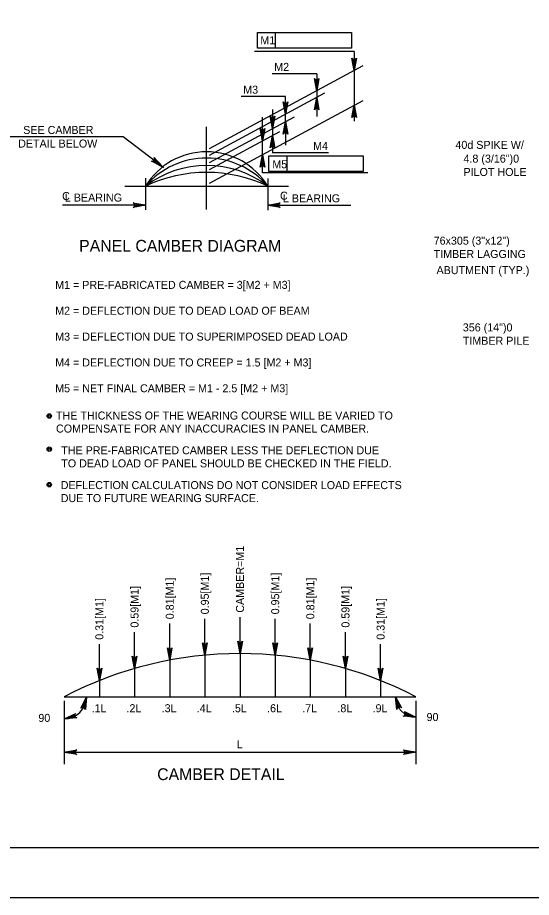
# Model space of a CAD drawing. Extents: x -8 to 75, y -110 to 0.
# Drawn here: x 45.04 to 52.74, y -88 to -74.81 of the extents above; entities that cross this region are included whole.
import ezdxf

# ---------------------------------------------------------------- set-up
doc = ezdxf.new("R2010")
doc.units = 0
for name, color, linetype in [('1', 7, 'Continuous'), ('2', 7, 'Continuous'), ('3', 7, 'Continuous'), ('4', 7, 'Continuous'), ('5', 7, 'Continuous'), ('63', 7, 'Continuous')]:
    doc.layers.add(name, color=color, linetype=linetype)

msp = doc.modelspace()

# ---------------------------------------------------------------- linework, layer by layer
at = {"layer": '1'}
msp.add_lwpolyline([(35.75, -87.25), (67.25, -87.25), (67.25, -66.75), (35.75, -66.75)], close=True, dxfattribs=at)
at = {"layer": '2'}
for p, q in [((46.649, -77.334), (49.101, -77.334)), ((45.742, -84.992), (51.008, -84.992))]:
    msp.add_line(p, q, dxfattribs=at)
at = {"layer": '4'}
for p, q in [((47.848, -84.368), (47.848, -84.992)), ((48.375, -84.344), (48.375, -84.992)), ((48.902, -84.368), (48.902, -84.992)), ((46.795, -84.568), (46.795, -84.992)), ((47.322, -84.442), (47.322, -84.992)), ((49.428, -84.442), (49.428, -84.992)), ((49.955, -84.568), (49.955, -84.992)), ((46.268, -84.749), (46.268, -84.992)), ((50.482, -84.749), (50.482, -84.992)), ((46.268, -84.992), (46.268, -84.992)), ((46.795, -84.992), (46.795, -84.992)), ((47.322, -84.992), (47.322, -84.992)), ((47.848, -84.992), (47.848, -84.992)), ((48.375, -84.992), (48.375, -84.992)), ((48.902, -84.992), (48.902, -84.992)), ((49.428, -84.992), (49.428, -84.992)), ((49.955, -84.992), (49.955, -84.992)), ((50.482, -84.992), (50.482, -84.992))]:
    msp.add_line(p, q, dxfattribs=at)
for centre, radius, start, end in [((47.875, -77.887), 1.069, 31.1159, 148.8841), ((47.875, -78.117), 1.205, 40.5509, 139.4492), ((47.875, -78.53), 1.506, 52.5765, 127.4235), ((47.875, -79.258), 2.13, 64.5513, 115.4487), ((48.375, -90.018), 5.675, 62.3509, 117.6491)]:
    msp.add_arc(centre, radius, start, end, dxfattribs=at)
at = {"layer": '5'}
for p, q in [((48.635, -75.03), (48.909, -75.03)), ((48.635, -75.266), (48.635, -75.03)), ((48.909, -75.266), (48.909, -75.03)), ((48.909, -75.03), (50.047, -75.03)), ((50.047, -75.03), (50.047, -75.266)), ((50.086, -75.315), (48.592, -75.315)), ((50.047, -75.266), (48.635, -75.266)), ((50.086, -75.315), (50.086, -76.358)), ((47.918, -76.771), (50.222, -75.526)), ((49.524, -75.647), (48.858, -75.647)), ((49.524, -75.647), (49.524, -76.29)), ((47.918, -76.87), (49.646, -75.936)), ((49.058, -75.989), (48.391, -75.989)), ((49.058, -76.413), (49.058, -75.989)), ((47.918, -77.291), (50.222, -76.047)), ((48.862, -76.184), (48.862, -76.832)), ((47.918, -76.981), (49.19, -76.294)), ((48.71, -77.136), (48.71, -76.298)), ((47.875, -77.684), (47.875, -76.446)), ((47.918, -77.085), (48.971, -76.516)), ((49.058, -76.413), (49.058, -76.719)), ((46.624, -76.593), (44.917, -76.593)), ((47.216, -77.044), (46.624, -76.593)), ((48.806, -76.879), (49.08, -76.879)), ((48.806, -77.115), (48.806, -76.879)), ((49.703, -76.832), (48.862, -76.832)), ((49.08, -77.115), (49.08, -76.879)), ((49.08, -76.879), (50.218, -76.879)), ((50.218, -76.879), (50.218, -77.115)), ((50.291, -77.136), (48.71, -77.136)), ((50.218, -77.115), (48.806, -77.115)), ((46.96, -77.212), (46.96, -77.689)), ((48.79, -77.218), (48.79, -77.694)), ((46.96, -77.62), (45.714, -77.62)), ((48.79, -77.62), (50.036, -77.62)), ((47.322, -84.442), (47.322, -83.894)), ((47.848, -84.368), (47.848, -83.82)), ((48.375, -84.344), (48.375, -83.795)), ((48.902, -84.368), (48.902, -83.82)), ((49.428, -84.442), (49.428, -83.894)), ((46.795, -84.568), (46.795, -84.02)), ((49.955, -84.568), (49.955, -84.02)), ((46.268, -84.749), (46.268, -84.201)), ((50.482, -84.749), (50.482, -84.201)), ((45.742, -85.054), (45.742, -86.002)), ((51.008, -85.054), (51.008, -86.002)), ((45.742, -85.822), (51.008, -85.822))]:
    msp.add_line(p, q, dxfattribs=at)
for points in [[(50.086, -75.599), (50.051, -75.413), (50.061, -75.427), (50.074, -75.434), (50.086, -75.436), (50.099, -75.434), (50.111, -75.427), (50.121, -75.413), (50.086, -75.599), (50.111, -75.427), (50.099, -75.434), (50.086, -75.599), (50.086, -75.436), (50.074, -75.434), (50.086, -75.599), (50.061, -75.427)], [(49.524, -75.903), (49.489, -75.717), (49.499, -75.731), (49.511, -75.738), (49.524, -75.74), (49.536, -75.738), (49.549, -75.731), (49.558, -75.717), (49.524, -75.903), (49.549, -75.731), (49.536, -75.738), (49.524, -75.903), (49.524, -75.74), (49.511, -75.738), (49.524, -75.903), (49.499, -75.731)], [(49.058, -76.254), (49.023, -76.067), (49.033, -76.082), (49.046, -76.089), (49.058, -76.091), (49.071, -76.089), (49.083, -76.082), (49.093, -76.067), (49.058, -76.254), (49.083, -76.082), (49.071, -76.089), (49.058, -76.254), (49.058, -76.091), (49.046, -76.089), (49.058, -76.254), (49.033, -76.082)], [(49.524, -76.002), (49.558, -76.189), (49.549, -76.174), (49.536, -76.167), (49.524, -76.165), (49.511, -76.167), (49.499, -76.174), (49.489, -76.189), (49.524, -76.002), (49.499, -76.174), (49.511, -76.167), (49.524, -76.002), (49.524, -76.165), (49.536, -76.167), (49.524, -76.002), (49.549, -76.174)], [(50.086, -76.12), (50.121, -76.306), (50.111, -76.292), (50.099, -76.284), (50.086, -76.282), (50.074, -76.284), (50.061, -76.292), (50.051, -76.306), (50.086, -76.12), (50.061, -76.292), (50.074, -76.284), (50.086, -76.12), (50.086, -76.282), (50.099, -76.284), (50.086, -76.12), (50.111, -76.292)], [(48.862, -76.471), (48.828, -76.285), (48.837, -76.299), (48.85, -76.306), (48.862, -76.308), (48.875, -76.306), (48.887, -76.299), (48.897, -76.285), (48.862, -76.471), (48.887, -76.299), (48.875, -76.306), (48.862, -76.471), (48.862, -76.308), (48.85, -76.306), (48.862, -76.471), (48.837, -76.299)], [(49.058, -76.365), (49.093, -76.552), (49.083, -76.537), (49.071, -76.53), (49.058, -76.528), (49.046, -76.53), (49.033, -76.537), (49.023, -76.552), (49.058, -76.365), (49.033, -76.537), (49.046, -76.53), (49.058, -76.365), (49.058, -76.528), (49.071, -76.53), (49.058, -76.365), (49.083, -76.537)], [(48.71, -76.656), (48.675, -76.47), (48.685, -76.484), (48.698, -76.492), (48.71, -76.494), (48.723, -76.492), (48.735, -76.484), (48.745, -76.47), (48.71, -76.656), (48.735, -76.484), (48.723, -76.492), (48.71, -76.656), (48.71, -76.494), (48.698, -76.492), (48.71, -76.656), (48.685, -76.484)], [(48.862, -76.574), (48.897, -76.761), (48.887, -76.746), (48.875, -76.739), (48.862, -76.737), (48.85, -76.739), (48.837, -76.746), (48.828, -76.761), (48.862, -76.574), (48.837, -76.746), (48.85, -76.739), (48.862, -76.574), (48.862, -76.737), (48.875, -76.739), (48.862, -76.574), (48.887, -76.746)], [(47.216, -77.044), (47.047, -76.959), (47.064, -76.96), (47.078, -76.954), (47.087, -76.946), (47.093, -76.935), (47.095, -76.92), (47.089, -76.904), (47.216, -77.044), (47.095, -76.92), (47.093, -76.935), (47.216, -77.044), (47.087, -76.946), (47.078, -76.954), (47.216, -77.044), (47.064, -76.96)], [(48.71, -76.863), (48.745, -77.05), (48.735, -77.035), (48.723, -77.028), (48.71, -77.026), (48.698, -77.028), (48.685, -77.035), (48.675, -77.05), (48.71, -76.863), (48.685, -77.035), (48.698, -77.028), (48.71, -76.863), (48.71, -77.026), (48.723, -77.028), (48.71, -76.863), (48.735, -77.035)], [(46.96, -77.62), (46.773, -77.654), (46.788, -77.644), (46.795, -77.632), (46.797, -77.62), (46.795, -77.607), (46.788, -77.594), (46.773, -77.585), (46.96, -77.62), (46.788, -77.594), (46.795, -77.607), (46.96, -77.62), (46.797, -77.62), (46.795, -77.632), (46.96, -77.62), (46.788, -77.644)], [(48.79, -77.62), (48.977, -77.585), (48.962, -77.594), (48.955, -77.607), (48.953, -77.62), (48.955, -77.632), (48.962, -77.644), (48.977, -77.654), (48.79, -77.62), (48.962, -77.644), (48.955, -77.632), (48.79, -77.62), (48.953, -77.62), (48.955, -77.607), (48.79, -77.62), (48.962, -77.594)], [(48.375, -84.344), (48.34, -84.157), (48.35, -84.172), (48.362, -84.179), (48.375, -84.181), (48.387, -84.179), (48.4, -84.172), (48.41, -84.157), (48.375, -84.344), (48.4, -84.172), (48.387, -84.179), (48.375, -84.344), (48.375, -84.181), (48.362, -84.179), (48.375, -84.344), (48.35, -84.172)], [(47.322, -84.442), (47.287, -84.256), (47.297, -84.27), (47.309, -84.278), (47.322, -84.28), (47.334, -84.278), (47.347, -84.27), (47.356, -84.256), (47.322, -84.442), (47.347, -84.27), (47.334, -84.278), (47.322, -84.442), (47.322, -84.28), (47.309, -84.278), (47.322, -84.442), (47.297, -84.27)], [(47.848, -84.368), (47.813, -84.182), (47.823, -84.196), (47.836, -84.204), (47.848, -84.206), (47.861, -84.204), (47.873, -84.196), (47.883, -84.182), (47.848, -84.368), (47.873, -84.196), (47.861, -84.204), (47.848, -84.368), (47.848, -84.206), (47.836, -84.204), (47.848, -84.368), (47.823, -84.196)], [(48.902, -84.368), (48.867, -84.182), (48.877, -84.196), (48.889, -84.204), (48.902, -84.206), (48.914, -84.204), (48.927, -84.196), (48.936, -84.182), (48.902, -84.368), (48.927, -84.196), (48.914, -84.204), (48.902, -84.368), (48.902, -84.206), (48.889, -84.204), (48.902, -84.368), (48.877, -84.196)], [(49.428, -84.442), (49.393, -84.256), (49.403, -84.27), (49.416, -84.278), (49.428, -84.28), (49.441, -84.278), (49.453, -84.27), (49.463, -84.256), (49.428, -84.442), (49.453, -84.27), (49.441, -84.278), (49.428, -84.442), (49.428, -84.28), (49.416, -84.278), (49.428, -84.442), (49.403, -84.27)], [(46.795, -84.568), (46.76, -84.382), (46.77, -84.396), (46.782, -84.403), (46.795, -84.406), (46.807, -84.403), (46.82, -84.396), (46.83, -84.382), (46.795, -84.568), (46.82, -84.396), (46.807, -84.403), (46.795, -84.568), (46.795, -84.406), (46.782, -84.403), (46.795, -84.568), (46.77, -84.396)], [(49.955, -84.568), (49.92, -84.382), (49.93, -84.396), (49.942, -84.403), (49.955, -84.406), (49.967, -84.403), (49.98, -84.396), (49.99, -84.382), (49.955, -84.568), (49.98, -84.396), (49.967, -84.403), (49.955, -84.568), (49.955, -84.406), (49.942, -84.403), (49.955, -84.568), (49.93, -84.396)], [(46.268, -84.749), (46.233, -84.563), (46.243, -84.577), (46.256, -84.585), (46.268, -84.587), (46.281, -84.585), (46.293, -84.577), (46.303, -84.563), (46.268, -84.749), (46.293, -84.577), (46.281, -84.585), (46.268, -84.749), (46.268, -84.587), (46.256, -84.585), (46.268, -84.749), (46.243, -84.577)], [(50.482, -84.749), (50.447, -84.563), (50.457, -84.577), (50.469, -84.585), (50.482, -84.587), (50.494, -84.585), (50.507, -84.577), (50.517, -84.563), (50.482, -84.749), (50.507, -84.577), (50.494, -84.585), (50.482, -84.749), (50.482, -84.587), (50.469, -84.585), (50.482, -84.749), (50.457, -84.577)], [(46.073, -84.992), (46.058, -85.181), (46.052, -85.165), (46.042, -85.154), (46.03, -85.149), (46.018, -85.148), (46.004, -85.151), (45.99, -85.163), (46.073, -84.992), (46.004, -85.151), (46.018, -85.148), (46.073, -84.992), (46.03, -85.149), (46.042, -85.154), (46.073, -84.992), (46.052, -85.165)], [(50.704, -84.992), (50.793, -85.159), (50.779, -85.148), (50.765, -85.145), (50.752, -85.147), (50.741, -85.153), (50.731, -85.163), (50.726, -85.18), (50.704, -84.992), (50.731, -85.163), (50.741, -85.153), (50.704, -84.992), (50.752, -85.147), (50.765, -85.145), (50.704, -84.992), (50.779, -85.148)], [(51.008, -85.299), (50.819, -85.28), (50.836, -85.275), (50.846, -85.265), (50.852, -85.253), (50.853, -85.241), (50.85, -85.227), (50.839, -85.213), (51.008, -85.299), (50.85, -85.227), (50.853, -85.241), (51.008, -85.299), (50.852, -85.253), (50.846, -85.265), (51.008, -85.299), (50.836, -85.275)], [(45.742, -85.322), (45.913, -85.242), (45.902, -85.255), (45.898, -85.269), (45.899, -85.281), (45.904, -85.293), (45.915, -85.303), (45.931, -85.309), (45.742, -85.322), (45.915, -85.303), (45.904, -85.293), (45.742, -85.322), (45.899, -85.281), (45.898, -85.269), (45.742, -85.322), (45.902, -85.255)], [(45.742, -85.822), (45.928, -85.787), (45.914, -85.797), (45.906, -85.81), (45.904, -85.822), (45.906, -85.835), (45.914, -85.847), (45.928, -85.857), (45.742, -85.822), (45.914, -85.847), (45.906, -85.835), (45.742, -85.822), (45.904, -85.822), (45.906, -85.81), (45.742, -85.822), (45.914, -85.797)], [(51.008, -85.822), (50.822, -85.857), (50.836, -85.847), (50.844, -85.835), (50.846, -85.822), (50.844, -85.81), (50.836, -85.797), (50.822, -85.787), (51.008, -85.822), (50.836, -85.797), (50.844, -85.81), (51.008, -85.822), (50.846, -85.822), (50.844, -85.835), (51.008, -85.822), (50.836, -85.847)]]:
    msp.add_lwpolyline(points, dxfattribs=at)
for points in [[(49.504, -76.12), (49.543, -76.12), (49.524, -76.002)], [(47.143, -76.963), (47.119, -76.995), (47.227, -77.052)]]:
    msp.add_lwpolyline(points, close=True, dxfattribs=at)
for centre, radius in [((45.517, -80.781), 0.0333), ((45.517, -80.781), 0.0167), ((45.517, -81.278), 0.0333), ((45.517, -81.278), 0.0167), ((45.517, -81.811), 0.0333), ((45.517, -81.811), 0.0167)]:
    msp.add_circle(centre, radius, dxfattribs=at)
for centre, radius, start, end in [((45.741, -84.992), 0.33, 269.9999, 359.9946), ((51.008, -84.992), 0.305, 180.0058, 270.0052)]:
    msp.add_arc(centre, radius, start, end, dxfattribs=at)
at = {"layer": '63'}
msp.add_lwpolyline([(34, -88), (68, -88), (68, -66), (34, -66)], close=True, dxfattribs=at)

# ---------------------------------------------------------------- texts
at = {"layer": '3'}
for s, p in [('40d SPIKE W/', (51.602, -76.775)), ('4.8 (3/16")0', (51.723, -76.981)), ('PILOT HOLE', (51.723, -77.181)), ('76x305 (3"x12")', (51.276, -78.211)), ('TIMBER LAGGING', (51.276, -78.411)), ('ABUTMENT (TYP.)', (51.319, -78.653)), ('356 (14")0', (51.713, -79.512)), ('TIMBER PILE', (51.713, -79.712))]:
    msp.add_text(s, height=0.12, dxfattribs=at).set_placement(p)
at = {"layer": '5'}
for s, height, p in [('M1', 0.12, (48.679, -75.206)), ('M2', 0.12, (48.888, -75.605)), ('M3', 0.12, (48.423, -75.947)), ('SEE CAMBER', 0.12, (45.127, -76.551)), ('DETAIL BELOW', 0.12, (45.051, -76.755)), ('M4', 0.12, (49.47, -76.79)), ('M5', 0.12, (48.859, -77.065)), ('C', 0.12, (45.71, -77.542)), ('L BEARING', 0.12, (45.751, -77.565)), ('C', 0.12, (48.975, -77.537)), ('L BEARING', 0.12, (49.018, -77.576)), ('PANEL CAMBER DIAGRAM', 0.17717, (45.965, -78.317)), ('M1 = PRE-FABRICATED CAMBER = 3[M2 + M3]', 0.12, (45.606, -78.874)), ('M2 = DEFLECTION DUE TO DEAD LOAD OF BEAM', 0.12, (45.606, -79.262)), ('M3 = DEFLECTION DUE TO SUPERIMPOSED DEAD LOAD', 0.12, (45.606, -79.65)), ('M4 = DEFLECTION DUE TO CREEP = 1.5 [M2 + M3]', 0.12, (45.606, -80.038)), ('M5 = NET FINAL CAMBER = M1 - 2.5 [M2 + M3]', 0.12, (45.606, -80.425)), (' THE THICKNESS OF THE WEARING COURSE WILL BE VARIED TO', 0.12, (45.574, -80.834)), (' COMPENSATE FOR ANY INACCURACIES IN PANEL CAMBER.', 0.12, (45.574, -81.029)), ('THE PRE-FABRICATED CAMBER LESS THE DEFLECTION DUE', 0.12, (45.697, -81.355)), ('TO DEAD LOAD OF PANEL SHOULD BE CHECKED IN THE FIELD.', 0.12, (45.697, -81.551)), ('DEFLECTION CALCULATIONS DO NOT CONSIDER LOAD EFFECTS', 0.12, (45.689, -81.877)), ('DUE TO FUTURE WEARING SURFACE.', 0.12, (45.689, -82.072)), ('.2L', 0.12, (46.674, -85.223)), ('.3L', 0.12, (47.201, -85.223)), ('.6L', 0.12, (48.781, -85.223)), ('.8L', 0.12, (49.834, -85.223)), ('.9L', 0.12, (50.361, -85.223)), ('.1L', 0.12, (46.151, -85.223)), ('.4L', 0.12, (47.727, -85.223)), ('.5L', 0.12, (48.254, -85.223)), ('.7L', 0.12, (49.307, -85.223)), ('90', 0.12, (51.17, -85.355)), ('90', 0.12, (45.354, -85.368)), ('L', 0.12, (48.328, -85.763)), ('CAMBER DETAIL', 0.17717, (47.134, -86.241))]:
    msp.add_text(s, height=height, dxfattribs=at).set_placement(p)
for s, p in [('CAMBER=M1', (48.435, -83.73)), ('0.81[M1]', (47.382, -83.829)), ('0.95[M1]', (47.908, -83.755)), ('0.95[M1]', (48.962, -83.755)), ('0.81[M1]', (49.488, -83.829)), ('0.59[M1]', (46.855, -83.954)), ('0.59[M1]', (50.015, -83.954)), ('0.31[M1]', (46.328, -84.136)), ('0.31[M1]', (50.541, -84.136))]:
    msp.add_text(s, height=0.12, rotation=90, dxfattribs=at).set_placement(p)

doc.saveas('drawing.dxf')
